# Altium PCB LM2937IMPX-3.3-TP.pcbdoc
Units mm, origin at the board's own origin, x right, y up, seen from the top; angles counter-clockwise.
Board outline 21.27 x 19.5 mm, 2 copper layers (Top Layer, Bottom Layer), stack 0 mm thick; 1 components, 0 nets, 4 pads, 0 vias.
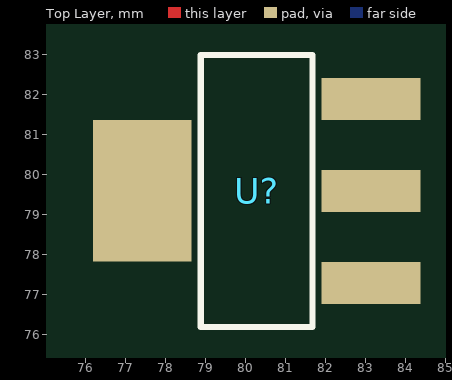
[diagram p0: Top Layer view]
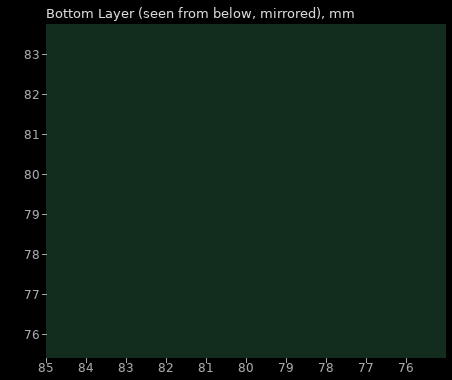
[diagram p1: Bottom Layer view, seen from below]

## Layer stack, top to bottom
Top Layer: signal copper (thickness not stored)
Bottom Layer: signal copper (thickness not stored)

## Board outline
91.119,69.85 69.85,69.85 69.85,89.352 91.119,89.352

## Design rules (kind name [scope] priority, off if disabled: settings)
PasteMaskExpansion "Paste Mask Expansion" [All] p1: expansion=0
SolderMaskExpansion "Solder Mask Expansion" [IsVia] p1: expansion=-25.4 istentingtop=TRUE
SolderMaskExpansion "Solder Mask Expansion" [All] p2: expansion=0.051 istentingtop=FALSE

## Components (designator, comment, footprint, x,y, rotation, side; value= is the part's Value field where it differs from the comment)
U? "LM2937IMPX-3.3-TP" SOT-223_L6.5-W3.5-P2.30-LS7.0-BR 80.29,79.601 r0 top

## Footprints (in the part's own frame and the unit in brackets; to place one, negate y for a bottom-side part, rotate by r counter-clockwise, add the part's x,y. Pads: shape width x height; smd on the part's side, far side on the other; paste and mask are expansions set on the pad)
SOT-223_L6.5-W3.5-P2.30-LS7.0-BR [mm]
  rect 2.465x1.05 smd: 1(2.857,-2.3) 2(2.857,0) 3(2.857,2.3)
  rect 2.465x3.54 smd: 4(-2.857,0)
  silkscreen extent -1.4,-3.4 1.4,3.4

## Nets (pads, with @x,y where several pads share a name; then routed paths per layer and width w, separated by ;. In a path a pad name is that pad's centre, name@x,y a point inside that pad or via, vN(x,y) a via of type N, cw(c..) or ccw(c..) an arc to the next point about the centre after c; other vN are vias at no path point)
pads on no net: U?.1 U?.2 U?.3 U?.4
